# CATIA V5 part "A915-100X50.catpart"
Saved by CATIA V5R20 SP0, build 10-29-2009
Part number: A915-100X50
Source: Unknown
Property "A": "50.000"
Property "ARTICLENO": "A915-100X50"
Property "BOMINFO": "A915-100X50"
Property "CODE": "A915-100X50"
Property "CREATOR": "CADENAS GmbH"
Property "D": "13.500"
Property "D1": "20.000"
Property "FORM": "A"
Property "L": "50.000"
Property "L1": "25.000"
Property "L2": "0.000"
Property "LINA": "A915-100X50"
Property "NB": "A915-100X50"
Property "NBSYN": "$CODE."
Property "NN": "A915"
Property "NT": "VDI 3357 Wear Plates, steel"
Property "SCREW": "M12x25"
Property "SUPPLIER": "CF"
Property "T": "13.000"
Property "W": "100.000"
Bounding box of the stored display mesh (mm): x 0 to 20, y 0 to 50, z -50 to 50
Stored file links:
  C:\Users\borellobunino\Desktop\3D X SITO CF\A915\GSB_OILLESS_G22501100050\CATIAV5\A915-100X50.catpart
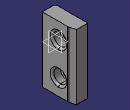
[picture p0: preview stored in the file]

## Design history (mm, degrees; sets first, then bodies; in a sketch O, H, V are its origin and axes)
Body1 "Geometry.1" (main body)
  Solid1 "A915-100X50.catpart": solid without history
